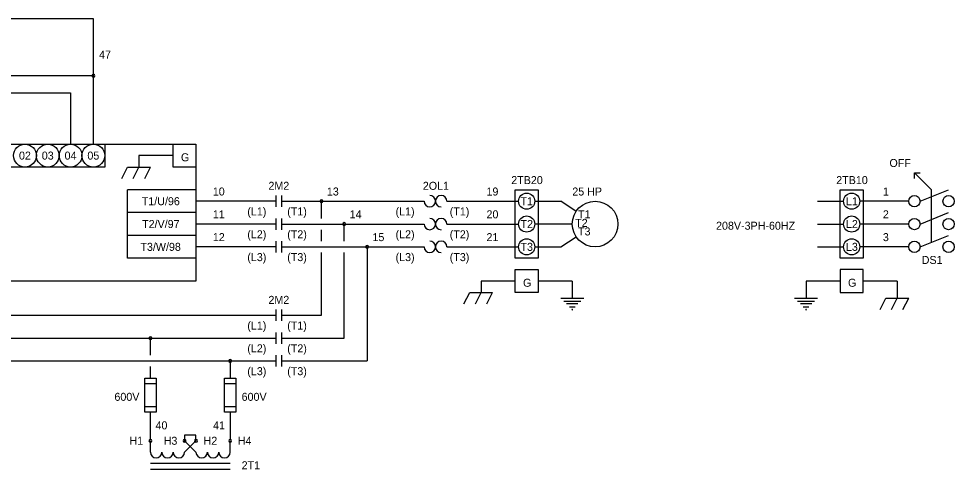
# Model space of a CAD drawing. Extents: x 10338 to 10578, y 10012 to 10165.
# Drawn here: x 10403.8 to 10481.8, y 10124.1 to 10161.6 of the extents above; entities that cross this region are included whole.
import ezdxf

# ---------------------------------------------------------------- set-up
doc = ezdxf.new("R2010")
doc.units = 0
for name, color, linetype in [('Level 61', 7, 'Continuous'), ('Level 62', 7, 'Continuous'), ('Level 63', 7, 'Continuous')]:
    doc.layers.add(name, color=color, linetype=linetype)

msp = doc.modelspace()

# ---------------------------------------------------------------- linework, layer by layer
at = {"layer": 'Level 61'}
for p, q in [((10410.042, 10161.615), (10401.492, 10161.615)), ((10410.042, 10151.165), (10410.042, 10161.615)), ((10410.042, 10156.865), (10400.067, 10156.865)), ((10379.642, 10155.44), (10408.142, 10155.44)), ((10408.142, 10155.44), (10408.142, 10151.165)), ((10416.692, 10150.215), (10413.842, 10150.215)), ((10413.842, 10150.215), (10413.842, 10149.265)), ((10445.192, 10147.365), (10447.092, 10147.365)), ((10479.867, 10142.995), (10479.867, 10147.365)), ((10425.242, 10146.415), (10418.592, 10146.415)), ((10425.717, 10146.415), (10437.592, 10146.415)), ((10429.042, 10144.99), (10429.042, 10146.415)), ((10439.492, 10146.415), (10445.429, 10146.415)), ((10446.854, 10146.415), (10448.992, 10146.415)), ((10450.261, 10145.569), (10448.992, 10146.415)), ((10470.367, 10146.415), (10472.504, 10146.415)), ((10477.967, 10146.415), (10473.889, 10146.415)), ((10425.242, 10144.515), (10418.592, 10144.515)), ((10425.717, 10144.515), (10437.592, 10144.515)), ((10429.042, 10143.09), (10429.042, 10144.04)), ((10430.942, 10143.09), (10430.942, 10144.515)), ((10439.492, 10144.515), (10445.429, 10144.515)), ((10449.942, 10144.515), (10446.854, 10144.515)), ((10470.367, 10144.515), (10472.504, 10144.515)), ((10477.967, 10144.515), (10473.889, 10144.515)), ((10448.992, 10142.615), (10450.261, 10143.461)), ((10425.242, 10142.615), (10418.592, 10142.615)), ((10425.717, 10142.615), (10437.592, 10142.615)), ((10432.842, 10142.615), (10432.842, 10133.115)), ((10439.492, 10142.615), (10445.429, 10142.615)), ((10446.854, 10142.615), (10448.992, 10142.615)), ((10470.367, 10142.615), (10472.504, 10142.615)), ((10477.967, 10142.615), (10473.889, 10142.615)), ((10429.042, 10136.915), (10429.042, 10142.14)), ((10430.942, 10135.015), (10430.942, 10142.14)), ((10445.192, 10139.765), (10442.342, 10139.765)), ((10442.342, 10139.765), (10442.342, 10138.815)), ((10449.942, 10139.765), (10447.092, 10139.765)), ((10449.942, 10139.765), (10449.942, 10138.34)), ((10472.267, 10139.765), (10469.417, 10139.765)), ((10469.417, 10139.765), (10469.417, 10138.34)), ((10477.017, 10139.765), (10474.167, 10139.765)), ((10477.017, 10139.765), (10477.017, 10138.34)), ((10363.017, 10136.915), (10425.242, 10136.915)), ((10425.717, 10136.915), (10429.042, 10136.915)), ((10361.117, 10135.015), (10425.242, 10135.015)), ((10414.792, 10133.59), (10414.792, 10135.015)), ((10425.717, 10135.015), (10430.942, 10135.015)), ((10359.217, 10133.115), (10425.242, 10133.115)), ((10421.442, 10133.115), (10421.442, 10131.69)), ((10425.717, 10133.115), (10432.842, 10133.115)), ((10414.792, 10131.69), (10414.792, 10132.64)), ((10415.267, 10131.215), (10414.317, 10131.215)), ((10421.917, 10131.215), (10420.967, 10131.215)), ((10414.317, 10129.315), (10415.267, 10129.315)), ((10420.967, 10129.315), (10421.917, 10129.315)), ((10414.792, 10126.584), (10414.792, 10128.84)), ((10421.442, 10128.84), (10421.442, 10126.584)), ((10417.642, 10126.94), (10417.642, 10126.465)), ((10418.592, 10126.94), (10417.642, 10126.94)), ((10418.592, 10126.465), (10418.592, 10126.94))]:
    msp.add_line(p, q, dxfattribs=at)
for centre, radius in [((10404.342, 10150.215), 0.95), ((10406.242, 10150.215), 0.95), ((10408.142, 10150.215), 0.95), ((10410.042, 10150.215), 0.95), ((10446.142, 10146.415), 0.672), ((10473.217, 10146.415), 0.672), ((10446.142, 10144.515), 0.672), ((10473.217, 10144.515), 0.672), ((10446.142, 10142.615), 0.672), ((10473.217, 10142.615), 0.672)]:
    msp.add_circle(centre, radius, dxfattribs=at)
for centre, start, end in [((10410.042, 10156.865), 0, 180), ((10410.042, 10156.865), 180, 0), ((10429.042, 10146.415), 0, 180), ((10429.042, 10146.415), 180, 0), ((10430.942, 10144.515), 0, 180), ((10430.942, 10144.515), 180, 0), ((10432.842, 10142.615), 0, 180), ((10432.842, 10142.615), 180, 0), ((10414.792, 10135.015), 0, 180), ((10414.792, 10135.015), 180, 0), ((10421.442, 10133.115), 0, 180), ((10421.442, 10133.115), 180, 0)]:
    msp.add_arc(centre, 0.119, start, end, dxfattribs=at)
at = {"layer": 'Level 62'}
for p, q in [((10412.417, 10148.315), (10412.892, 10149.265)), ((10412.892, 10149.265), (10414.792, 10149.265)), ((10413.367, 10148.315), (10413.842, 10149.265)), ((10414.317, 10148.315), (10414.792, 10149.265)), ((10479.867, 10147.365), (10478.442, 10148.79)), ((10478.442, 10148.315), (10478.442, 10148.79)), ((10478.442, 10148.79), (10478.917, 10148.79)), ((10418.592, 10147.365), (10412.892, 10147.365)), ((10412.892, 10141.665), (10412.892, 10147.365)), ((10425.242, 10146.89), (10425.242, 10145.94)), ((10425.717, 10146.89), (10425.717, 10145.94)), ((10472.267, 10147.365), (10474.167, 10147.365)), ((10472.267, 10141.665), (10472.267, 10147.365)), ((10474.167, 10147.365), (10474.167, 10141.665)), ((10478.917, 10146.415), (10481.292, 10147.365)), ((10418.592, 10145.465), (10412.892, 10145.465)), ((10478.917, 10144.515), (10481.292, 10145.465)), ((10425.242, 10144.99), (10425.242, 10144.04)), ((10425.717, 10144.99), (10425.717, 10144.04)), ((10418.592, 10143.565), (10412.892, 10143.565)), ((10425.242, 10143.09), (10425.242, 10142.14)), ((10425.717, 10143.09), (10425.717, 10142.14)), ((10478.917, 10142.615), (10481.292, 10143.565)), ((10418.592, 10141.665), (10412.892, 10141.665)), ((10474.167, 10141.665), (10472.267, 10141.665)), ((10474.167, 10140.715), (10472.267, 10140.715)), ((10472.267, 10140.715), (10472.267, 10138.815)), ((10474.167, 10138.815), (10474.167, 10140.715)), ((10440.917, 10137.865), (10441.392, 10138.815)), ((10441.392, 10138.815), (10443.292, 10138.815)), ((10441.867, 10137.865), (10442.342, 10138.815)), ((10442.817, 10137.865), (10443.292, 10138.815)), ((10448.992, 10138.34), (10450.892, 10138.34)), ((10468.467, 10138.34), (10470.367, 10138.34)), ((10472.267, 10138.815), (10474.167, 10138.815)), ((10475.592, 10137.39), (10476.067, 10138.34)), ((10476.067, 10138.34), (10477.967, 10138.34)), ((10476.542, 10137.39), (10477.017, 10138.34)), ((10477.492, 10137.39), (10477.967, 10138.34)), ((10449.229, 10138.103), (10450.654, 10138.103)), ((10450.417, 10137.865), (10449.467, 10137.865)), ((10449.704, 10137.628), (10450.179, 10137.628)), ((10468.704, 10138.103), (10470.129, 10138.103)), ((10469.892, 10137.865), (10468.942, 10137.865)), ((10469.179, 10137.628), (10469.654, 10137.628)), ((10425.242, 10137.39), (10425.242, 10136.44)), ((10425.717, 10137.39), (10425.717, 10136.44)), ((10425.242, 10135.49), (10425.242, 10134.54)), ((10425.717, 10135.49), (10425.717, 10134.54)), ((10425.242, 10133.59), (10425.242, 10132.64)), ((10425.717, 10133.59), (10425.717, 10132.64)), ((10414.792, 10125.515), (10414.792, 10126.465)), ((10417.642, 10126.465), (10418.592, 10125.515)), ((10417.642, 10125.515), (10418.592, 10126.465)), ((10421.442, 10125.515), (10421.442, 10126.465)), ((10421.442, 10124.565), (10414.792, 10124.565)), ((10414.792, 10124.09), (10421.442, 10124.09))]:
    msp.add_line(p, q, dxfattribs=at)
for points in [[(10371.092, 10151.165), (10418.592, 10151.165), (10418.592, 10139.765), (10371.092, 10139.765)], [(10401.492, 10151.165), (10410.992, 10151.165), (10410.992, 10149.265), (10401.492, 10149.265)], [(10416.692, 10151.165), (10418.592, 10151.165), (10418.592, 10149.265), (10416.692, 10149.265)], [(10445.192, 10147.365), (10447.092, 10147.365), (10447.092, 10141.665), (10445.192, 10141.665)], [(10445.192, 10140.715), (10447.092, 10140.715), (10447.092, 10138.815), (10445.192, 10138.815)], [(10414.317, 10131.69), (10415.267, 10131.69), (10415.267, 10128.84), (10414.317, 10128.84)], [(10420.967, 10131.69), (10421.917, 10131.69), (10421.917, 10128.84), (10420.967, 10128.84)]]:
    msp.add_lwpolyline(points, close=True, dxfattribs=at)
for centre, radius in [((10478.442, 10146.415), 0.475), ((10481.292, 10146.415), 0.475), ((10451.842, 10144.515), 1.9), ((10478.442, 10144.515), 0.475), ((10481.292, 10144.515), 0.475), ((10478.442, 10142.615), 0.475), ((10481.292, 10142.615), 0.475)]:
    msp.add_circle(centre, radius, dxfattribs=at)
for centre, radius, start, end in [((10438.067, 10146.415), 0.475, 180, 90), ((10439.017, 10146.415), 0.475, 0, 270), ((10438.067, 10144.515), 0.475, 180, 90), ((10439.017, 10144.515), 0.475, 0, 270), ((10438.067, 10142.615), 0.475, 180, 90), ((10439.017, 10142.615), 0.475, 0, 270), ((10449.942, 10137.39), 0.0297, 0, 180), ((10449.942, 10137.39), 0.0297, 180, 0), ((10469.417, 10137.39), 0.0297, 0, 180), ((10469.417, 10137.39), 0.0297, 180, 0), ((10414.792, 10126.465), 0.119, 90, 270), ((10414.792, 10126.465), 0.119, 270, 90), ((10417.642, 10126.465), 0.119, 90, 270), ((10417.642, 10126.465), 0.119, 270, 90), ((10418.592, 10126.465), 0.119, 90, 270), ((10418.592, 10126.465), 0.119, 270, 90), ((10421.442, 10126.465), 0.119, 90, 270), ((10421.442, 10126.465), 0.119, 270, 90), ((10415.267, 10125.515), 0.475, 180, 0), ((10416.217, 10125.515), 0.475, 180, 0), ((10417.167, 10125.515), 0.475, 180, 0), ((10419.067, 10125.515), 0.475, 180, 0), ((10420.017, 10125.515), 0.475, 180, 0), ((10420.967, 10125.515), 0.475, 180, 0)]:
    msp.add_arc(centre, radius, start, end, dxfattribs=at)

# ---------------------------------------------------------------- texts
at = {"layer": 'Level 63'}
for s, height, p in [('47', 0.6667, (10410.518, 10158.291)), ('02', 0.6667, (10403.844, 10149.882)), ('03', 0.6667, (10405.744, 10149.882)), ('04', 0.6667, (10407.644, 10149.882)), ('05', 0.6667, (10409.544, 10149.882)), ('G', 0.667, (10417.337, 10149.741)), ('OFF', 0.6667, (10476.364, 10149.266)), ('2TB20', 0.6667, (10444.855, 10147.841)), ('2TB10', 0.6667, (10471.93, 10147.841)), ('2M2', 0.6667, (10424.627, 10147.366)), ('2OL1', 0.6667, (10437.49, 10147.366)), ('10', 0.6667, (10419.993, 10146.891)), ('13', 0.6667, (10429.494, 10146.891)), ('19', 0.6667, (10442.794, 10146.891)), ('25 HP', 0.6667, (10449.943, 10146.891)), ('1', 0.667, (10475.818, 10146.891)), ('T1/U/96', 0.6667, (10414.074, 10146.082)), ('T1', 0.6667, (10445.625, 10146.082)), ('L1', 0.6667, (10472.74, 10146.082)), ('11', 0.6667, (10419.993, 10144.991)), ('(L1)', 0.6667, (10422.868, 10145.228)), ('(T1)', 0.6667, (10426.193, 10145.228)), ('14', 0.6667, (10431.394, 10144.991)), ('(L1)', 0.6667, (10435.218, 10145.228)), ('(T1)', 0.6667, (10439.731, 10145.228)), ('20', 0.6667, (10442.793, 10144.991)), ('T1', 0.6667, (10450.418, 10144.991)), ('2', 0.667, (10475.818, 10144.991)), ('T2/V/97', 0.6667, (10414.101, 10144.182)), ('T2', 0.6667, (10445.626, 10144.182)), ('T2', 0.6667, (10450.181, 10144.278)), ('208V-3PH-60HZ', 0.66667, (10461.918, 10144.041)), ('L2', 0.6667, (10472.74, 10144.182)), ('12', 0.6667, (10419.994, 10143.091)), ('(L2)', 0.6667, (10422.868, 10143.328)), ('(T2)', 0.6667, (10426.193, 10143.328)), ('15', 0.6667, (10433.294, 10143.091)), ('(L2)', 0.6667, (10435.218, 10143.328)), ('(T2)', 0.6667, (10439.731, 10143.328)), ('21', 0.6667, (10442.793, 10143.091)), ('T3', 0.6667, (10450.418, 10143.566)), ('3', 0.667, (10475.818, 10143.091)), ('T3/W/98', 0.6667, (10413.961, 10142.282)), ('T3', 0.6667, (10445.626, 10142.282)), ('L3', 0.6667, (10472.74, 10142.282)), ('(L3)', 0.6667, (10422.868, 10141.428)), ('(T3)', 0.6667, (10426.193, 10141.428)), ('(L3)', 0.6667, (10435.218, 10141.428)), ('(T3)', 0.6667, (10439.731, 10141.428)), ('DS1', 0.6667, (10479.052, 10141.191)), ('G', 0.667, (10445.837, 10139.291)), ('G', 0.667, (10472.912, 10139.291)), ('2M2', 0.6667, (10424.627, 10137.866)), ('(L1)', 0.6667, (10422.868, 10135.728)), ('(T1)', 0.6667, (10426.193, 10135.728)), ('(L2)', 0.6667, (10422.868, 10133.828)), ('(T2)', 0.6667, (10426.193, 10133.828)), ('(L3)', 0.6667, (10422.868, 10131.928)), ('(T3)', 0.6667, (10426.193, 10131.928)), ('600V', 0.6667, (10411.796, 10129.791)), ('600V', 0.6667, (10422.393, 10129.791)), ('40', 0.6667, (10415.218, 10127.416)), ('41', 0.6667, (10420.018, 10127.416)), ('H1', 0.6667, (10413.046, 10126.132)), ('H3', 0.6667, (10415.897, 10126.132)), ('H2', 0.6667, (10419.222, 10126.132)), ('H4', 0.6667, (10422.072, 10126.132)), ('2T1', 0.6667, (10422.393, 10124.091))]:
    msp.add_text(s, height=height, dxfattribs=at).set_placement(p)

doc.saveas('drawing.dxf')
